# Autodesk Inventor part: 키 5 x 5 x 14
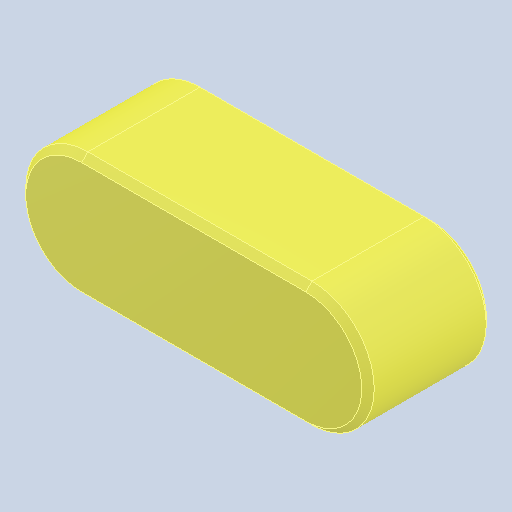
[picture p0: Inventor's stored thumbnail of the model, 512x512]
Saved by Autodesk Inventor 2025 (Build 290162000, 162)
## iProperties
Created: 2024-07
Part Number: 키 5 x 5 x 14
Material: 강철, 연강
Description: 키 및 해당 키홈
Document SubType Name: Modeling
Designer: hsj03
Density: 7.85 g/cm^3
Appearance: 기본값
Author: jhkim
Sending System: Autodesk Inventor 2025
Preprocessor: ST-DEVELOPER v20
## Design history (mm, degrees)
feature "Solid1"
node "솔리드1"
